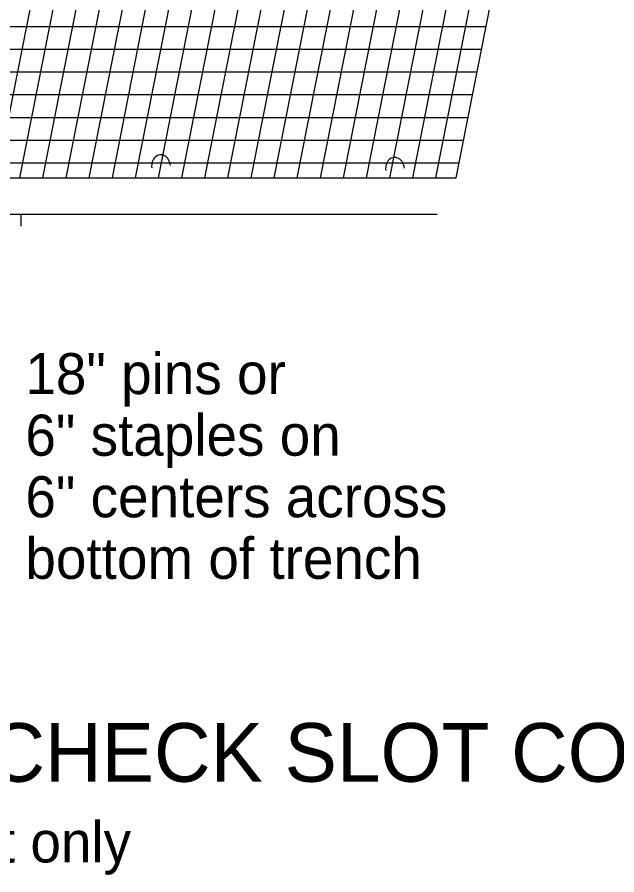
# Model space of a CAD drawing. Extents: x 1083.1 to 1117.1, y 719.4 to 741.4.
# Drawn here: x 1100.441 to 1102.488, y 732.703 to 735.628 of the extents above; entities that cross this region are included whole.
import ezdxf

# ---------------------------------------------------------------- set-up
doc = ezdxf.new("R2010")
doc.units = 0
doc.layers.add('ST_Details', color=7, linetype='Continuous')
doc.layers.add('ST_Text', color=7, linetype='Continuous')

msp = doc.modelspace()

# ---------------------------------------------------------------- linework, layer by layer
at = {"layer": 'ST_Details'}
for p, q in [((1100.3719, 735.0804), (1101.0391, 738.4558)), ((1100.4507, 735.0804), (1101.1179, 738.4558)), ((1100.5296, 735.0804), (1101.1968, 738.4558)), ((1100.6085, 735.0804), (1101.2756, 738.4558)), ((1100.6874, 735.0804), (1101.3546, 738.4558)), ((1100.7662, 735.0804), (1101.4335, 738.4558)), ((1100.8451, 735.0804), (1101.5123, 738.4558)), ((1100.924, 735.0804), (1101.5911, 738.4558)), ((1101.0029, 735.0804), (1101.67, 738.4558)), ((1101.0818, 735.0804), (1101.7489, 738.4558)), ((1101.1606, 735.0804), (1101.8277, 738.4558)), ((1101.2396, 735.0804), (1101.9066, 738.4558)), ((1101.3184, 735.0804), (1101.9855, 738.4558)), ((1101.3973, 735.0804), (1102.0644, 738.4558)), ((1101.4761, 735.0804), (1102.1433, 738.4558)), ((1101.5551, 735.0804), (1102.2221, 738.4558)), ((1101.6339, 735.0804), (1102.3011, 738.4558)), ((1101.7128, 735.0804), (1102.3799, 738.4558)), ((1101.7917, 735.0804), (1102.4588, 738.4558)), ((1101.8705, 735.0804), (1102.2745, 737.1242)), ((1101.9395, 735.0804), (1102.332, 737.0662)), ((1100.2128, 735.5961), (1102.0413, 735.5961)), ((1100.1806, 735.5188), (1102.026, 735.5188)), ((1100.138, 735.4414), (1102.0107, 735.4414)), ((1100.083, 735.364), (1101.9954, 735.364)), ((1100.0096, 735.2866), (1101.9801, 735.2866)), ((1099.9112, 735.2093), (1101.9649, 735.2093)), ((1099.7618, 735.1319), (1101.9496, 735.1319)), ((1098.7973, 735.0804), (1101.9394, 735.0804)), ((1099.4858, 735.0804), (1101.9394, 735.0804)), ((1098.7973, 734.9563), (1101.8748, 734.9563)), ((1100.4554, 734.9156), (1100.4554, 734.9563))]:
    msp.add_line(p, q, dxfattribs=at)
for centre in [(1100.9328, 735.118), (1101.7311, 735.109)]:
    msp.add_ellipse(centre, major_axis=(-0.0049, 0.0407), ratio=0.788117, start_param=4.712337, end_param=7.85393, dxfattribs=at)

# ---------------------------------------------------------------- texts
at = {"layer": 'ST_Text'}
for s, height, p in [('18" pins or', 0.14, (1100.4695, 734.3425)), ('6" staples on', 0.14, (1100.4695, 734.1325)), ('6" centers across', 0.14, (1100.4695, 733.9225)), ('bottom of trench', 0.14, (1100.4695, 733.7125)), ('CHECK SLOT CONSTRUCTION DETAILS', 0.2, (1100.3435, 733.0205)), ('Overlap should be slit only', 0.14, (1098.6344, 732.7452))]:
    msp.add_text(s, height=height, dxfattribs=at).set_placement(p)

doc.saveas('drawing.dxf')
